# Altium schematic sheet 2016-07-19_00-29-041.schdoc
size 220 x 124 mm; SheetNumber: 1; SheetTotal: 1
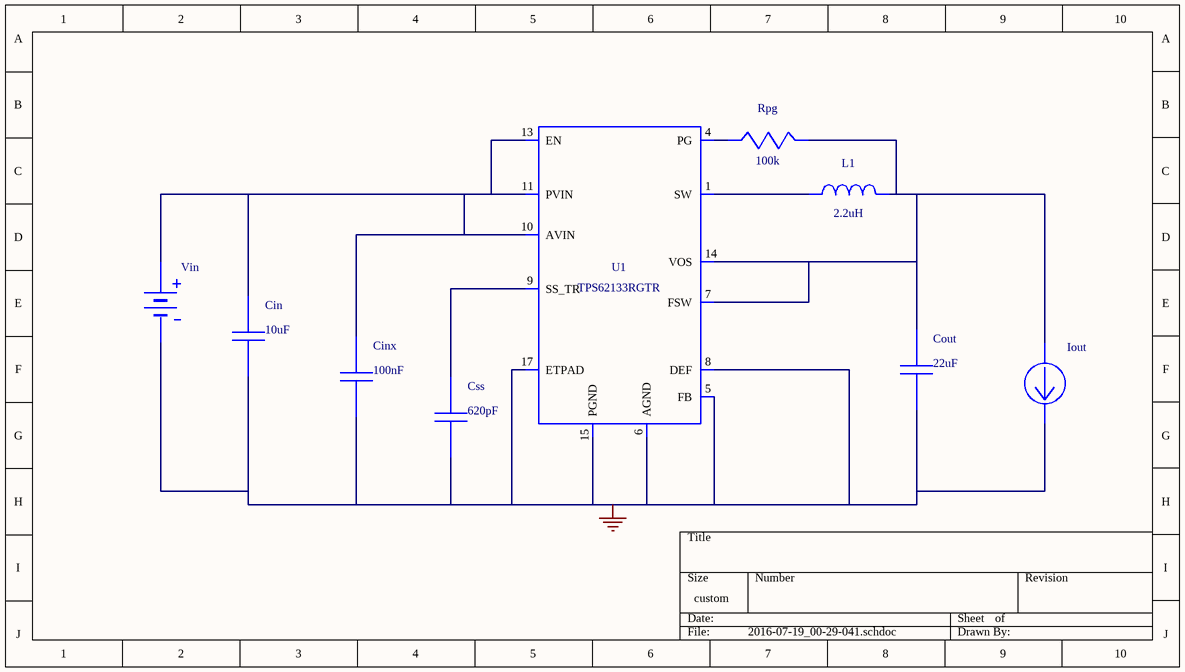
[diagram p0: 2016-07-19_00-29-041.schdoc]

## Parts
Cin  value 10uF  (hidden comment: TMK316BJ106KL-T)
Cinx  value 100nF  (hidden comment: C0603C104K3RACTU)
Cout  value 22uF  (hidden comment: GRM31CR61A226KE19L)
Css  value 620pF  (hidden comment: GRM1555C1E621JA01D)
Iout  WB_CURRENT_LOAD  (value not drawn)
L1  value 2.2uH  (hidden comment: SRN8040-2R2Y)
Rpg  value 100k  (hidden comment: CRCW0402100KFKED)
U1  TPS62131RGTR  (value not drawn)
Vin  WB_BATTERY  (value not drawn)

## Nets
0: Cin.2 Cinx.2 Cout.2 Css.2 Iout.2(-) U1.5(FB) U1.6(AGND) U1.8(DEF) U1.15(PGND) U1.16(PGND) U1.17(ETPAD) Vin.2(-)
NetCin_1: Cin.1 Cinx.1 U1.10(AVIN) U1.11(PVIN) U1.12(PVIN) U1.13(EN) Vin.1(+)
NetCout_1: Cout.1 Iout.1(+) L1.2 Rpg.1 U1.7(FSW) U1.14(VOS)
NetCss_1: Css.1 U1.9(SS_TR)
NetL1_1: L1.1 U1.1(SW) U1.2(SW) U1.3(SW)
NetRpg_2: Rpg.2 U1.4(PG)

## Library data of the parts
Cin = TMK316BJ106KL-T: Manufacturer Name: Taiyo Yuden
Cinx = C0603C104K3RACTU: Manufacturer Name: Kemet
Cout = GRM31CR61A226KE19L: GRM31CR61A226KE1; Manufacturer Name: MuRata
Css = GRM1555C1E621JA01D: GRM1555C1E621JA0; Manufacturer Name: MuRata
L1 = SRN8040-2R2Y: Manufacturer Name: Bourns
Rpg = CRCW0402100KFKED: Manufacturer Name: Vishay-Dale
U1 = TPS62131RGTR: TPS62133RGTR; Manufacturer Name: Texas Instruments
